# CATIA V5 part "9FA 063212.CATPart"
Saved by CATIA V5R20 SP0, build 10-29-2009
Part number: 9FA 063212
Revision: ANY
Definition: UNKNOWN
Nomenclature: 9FA 063212
Source: Unknown
Bounding box of the stored display mesh (mm): x -3 to 3, y -9.95 to 10.05, z -3 to 3
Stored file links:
  C:\Users\Utente\Desktop\IO LAVORO\3D X SITO CF\CUMSA\3D files FA\FA 0632SF\9FA 063212.CATPart

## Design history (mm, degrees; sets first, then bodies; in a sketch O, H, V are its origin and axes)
Body1 "Cortar-Extruir5" (main body)
  Solid1: solid without history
